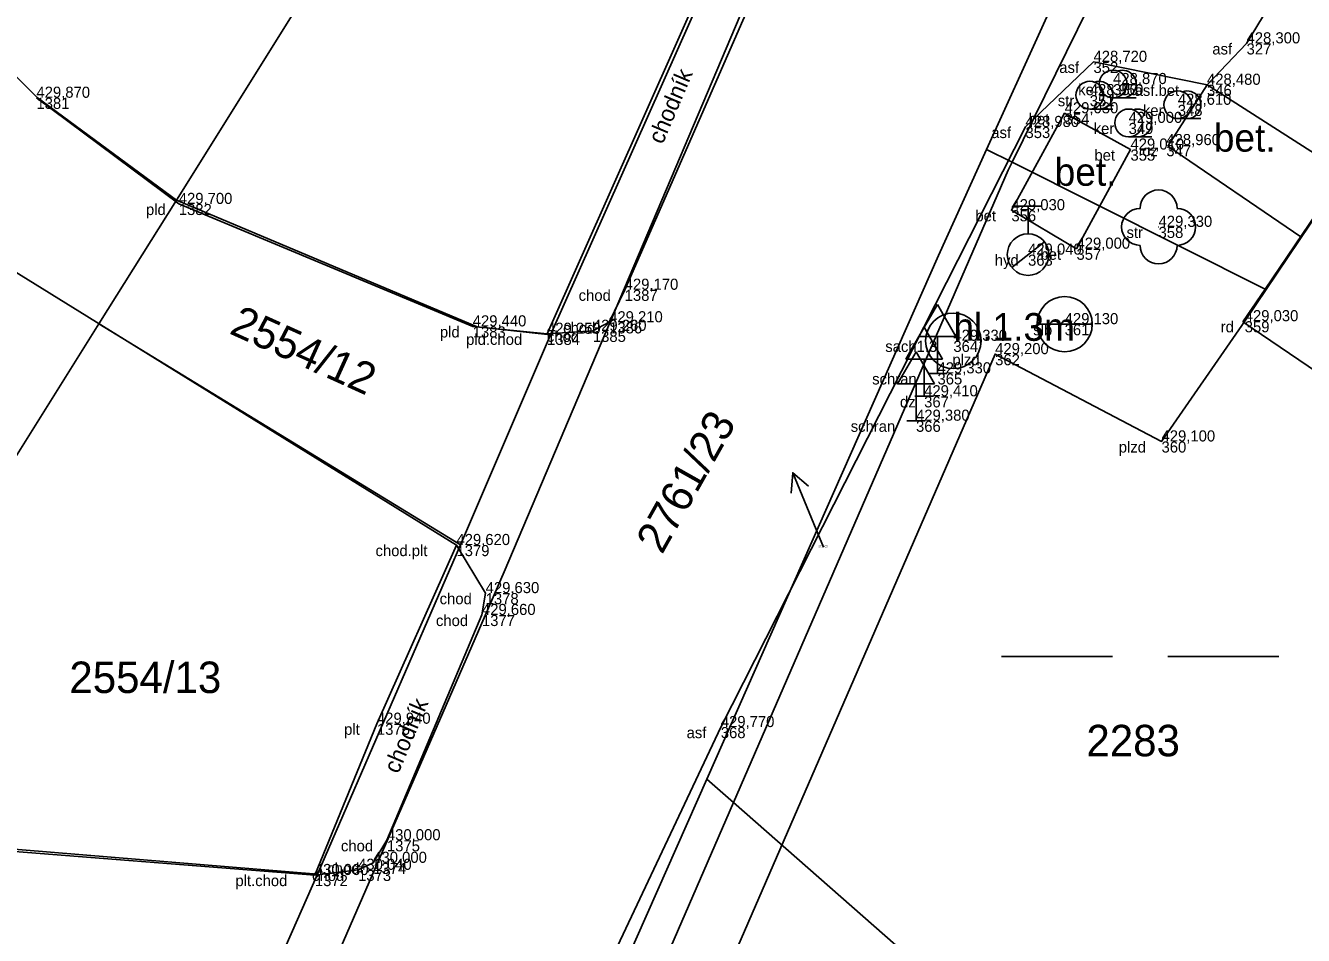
# Model space of a CAD drawing. Extents: x -747792 to -745414, y -1093712 to -1091463.
# Drawn here: x -746629.9 to -746595.34, y -1092966.57 to -1092941.98 of the extents above; entities that cross this region are included whole.
import ezdxf

# ---------------------------------------------------------------- set-up
doc = ezdxf.new("R2010")
doc.units = 0
for name, color, linetype in [('Budovy', 7, 'Continuous'), ('Doplňkové značky', 7, 'Continuous'), ('Hladina', 7, 'Continuous'), ('Koleje_dopravní prvky', 7, 'Continuous'), ('Nezařazené objekty', 7, 'Continuous'), ('Nivelační značky_hrany', 7, 'Continuous'), ('Názvy obcí_ulic', 7, 'Continuous'), ('Popisy objektů_povrchů', 7, 'Continuous'), ('Pracovní_bod JDTM STC_VC - výška', 7, 'Continuous'), ('Pracovní_bod PPBP - číslo', 7, 'Continuous'), ('Pracovní_bod ZPBP - číslo', 7, 'Continuous'), ('Rozhraní ploch', 7, 'Continuous'), ('Stromy_porost', 7, 'Continuous'), ('Výškopis', 7, 'Continuous'), ('Čísla popisná_parcelní', 7, 'Continuous')]:
    doc.layers.add(name, color=color, linetype=linetype)

msp = doc.modelspace()

# ---------------------------------------------------------------- linework, layer by layer
at = {"layer": 'Budovy'}
for points in [[(-746603.51, -1092959.03), (-746600.51, -1092959.03)], [(-746599.01, -1092959.03), (-746596.01, -1092959.03)]]:
    msp.add_lwpolyline(points, dxfattribs=at)
at = {"layer": 'Doplňkové značky'}
for points in [[(-746609.194, -1092954.622), (-746609.155, -1092954.064), (-746608.732, -1092954.431)], [(-746609.155, -1092954.064), (-746608.58, -1092955.45)], [(-746608.32, -1092956.08), (-746608.58, -1092955.45)]]:
    msp.add_lwpolyline(points, dxfattribs=at)
at = {"layer": 'Hladina'}
for p, q in [((-746596.88, -1092942.46), (-746596.88, -1092942.46)), ((-746601.02, -1092942.96), (-746601.02, -1092942.96)), ((-746600.49, -1092943.56), (-746600.49, -1092943.56)), ((-746597.95, -1092943.58), (-746597.95, -1092943.58)), ((-746629.61, -1092943.93), (-746629.61, -1092943.93)), ((-746601.12, -1092943.86), (-746601.12, -1092943.86)), ((-746598.74, -1092944.12), (-746598.74, -1092944.12)), ((-746601.8, -1092944.35), (-746601.8, -1092944.35)), ((-746600.07, -1092944.61), (-746600.07, -1092944.61)), ((-746602.86, -1092944.72), (-746602.86, -1092944.72)), ((-746600.02, -1092945.33), (-746600.02, -1092945.33)), ((-746599.05, -1092945.21), (-746599.05, -1092945.21)), ((-746625.76, -1092946.8), (-746625.76, -1092946.8)), ((-746603.24, -1092946.97), (-746603.24, -1092946.97)), ((-746599.26, -1092947.42), (-746599.26, -1092947.42)), ((-746601.48, -1092948.01), (-746601.48, -1092948.01)), ((-746602.79, -1092948.17), (-746602.79, -1092948.17)), ((-746613.7, -1092949.12), (-746613.7, -1092949.12)), ((-746617.81, -1092950.11), (-746617.81, -1092950.11)), ((-746614.12, -1092950), (-746614.12, -1092950)), ((-746601.8, -1092950.05), (-746601.8, -1092950.05)), ((-746596.93, -1092949.97), (-746596.93, -1092949.97)), ((-746615.8, -1092950.31), (-746615.8, -1092950.31)), ((-746614.56, -1092950.23), (-746614.56, -1092950.23)), ((-746604.81, -1092950.5), (-746604.81, -1092950.5)), ((-746603.68, -1092950.86), (-746603.68, -1092950.86)), ((-746605.24, -1092951.38), (-746605.24, -1092951.38)), ((-746605.6, -1092952), (-746605.6, -1092952)), ((-746605.82, -1092952.66), (-746605.82, -1092952.66)), ((-746599.18, -1092953.22), (-746599.18, -1092953.22)), ((-746618.25, -1092956.02), (-746618.25, -1092956.02)), ((-746617.46, -1092957.32), (-746617.46, -1092957.32)), ((-746617.56, -1092957.91), (-746617.56, -1092957.91)), ((-746620.4, -1092960.85), (-746620.4, -1092960.85)), ((-746611.1, -1092960.94), (-746611.1, -1092960.94)), ((-746620.13, -1092964), (-746620.13, -1092964)), ((-746620.5, -1092964.61), (-746620.5, -1092964.61)), ((-746622.08, -1092964.94), (-746622.08, -1092964.94)), ((-746620.91, -1092964.8), (-746620.91, -1092964.8))]:
    msp.add_line(p, q, dxfattribs=at)
at = {"layer": 'Nezařazené objekty'}
for points in [[(-746629.61, -1092943.93), (-746625.76, -1092946.8), (-746617.81, -1092950.11), (-746615.8, -1092950.31), (-746607.89, -1092932.54), (-746608.65, -1092931.35)], [(-746599.01, -1092945.24), (-746595.41, -1092947.69)], [(-746639.49, -1092962.88), (-746634.89, -1092963.93), (-746622.08, -1092964.94), (-746620.4, -1092960.85), (-746618.25, -1092956.02), (-746632.9, -1092946.96)], [(-746596.93, -1092949.97), (-746599.18, -1092953.22), (-746603.68, -1092950.86), (-746611.12, -1092967.97), (-746609.88, -1092968.61)]]:
    msp.add_lwpolyline(points, dxfattribs=at)
at = {"layer": 'Nivelační značky_hrany'}
for points in [[(-746567.47, -1092928.76), (-746566.95, -1092927.82), (-746569.47, -1092926.26), (-746577.49, -1092922.09), (-746580.71, -1092921), (-746582.05, -1092920.75), (-746583.67, -1092921.02), (-746585.64, -1092922.33), (-746587.16, -1092923.77), (-746589.64, -1092927.2), (-746592.28, -1092931.27), (-746593.72, -1092934.95), (-746594.32, -1092936.39), (-746593.98, -1092937.68), (-746596.88, -1092942.46), (-746597.95, -1092943.58)], [(-746615.8, -1092950.31), (-746614.56, -1092950.23), (-746614.12, -1092950), (-746613.7, -1092949.12), (-746606.9, -1092933.61), (-746606.5, -1092932.47), (-746606.65, -1092931.53), (-746607.26, -1092930.61), (-746608.07, -1092930.18)], [(-746613, -1092975.05), (-746615.68, -1092973.55), (-746616.37, -1092972.41), (-746614.88, -1092968.94), (-746611.1, -1092960.94), (-746602.86, -1092944.72), (-746601.02, -1092942.96), (-746597.95, -1092943.58)], [(-746599.01, -1092945.24), (-746597.95, -1092943.58), (-746594.24, -1092945.95)], [(-746601.48, -1092948.01), (-746603.24, -1092946.97), (-746601.8, -1092944.35), (-746600.02, -1092945.33), (-746601.48, -1092948.01)], [(-746622.08, -1092964.94), (-746620.91, -1092964.8), (-746620.5, -1092964.61), (-746620.13, -1092964), (-746617.56, -1092957.91), (-746617.46, -1092957.32), (-746618.25, -1092956.02)]]:
    msp.add_lwpolyline(points, dxfattribs=at)
at = {"layer": 'Názvy obcí_ulic'}
for p, q in [((-746605.24, -1092949.514), (-746605.74, -1092950.38)), ((-746605.24, -1092949.514), (-746604.74, -1092950.38)), ((-746605.6, -1092950.134), (-746606.1, -1092951)), ((-746605.6, -1092950.134), (-746605.1, -1092951)), ((-746605.74, -1092950.38), (-746604.74, -1092950.38)), ((-746605.24, -1092951.38), (-746605.24, -1092950.38)), ((-746605.82, -1092950.794), (-746606.32, -1092951.66)), ((-746605.82, -1092950.794), (-746605.32, -1092951.66)), ((-746606.1, -1092951), (-746605.1, -1092951)), ((-746605.6, -1092952), (-746605.6, -1092951)), ((-746605.49, -1092951.38), (-746604.99, -1092951.38)), ((-746606.32, -1092951.66), (-746605.32, -1092951.66)), ((-746605.82, -1092952.66), (-746605.82, -1092951.66)), ((-746605.85, -1092952), (-746605.35, -1092952)), ((-746606.07, -1092952.66), (-746605.57, -1092952.66))]:
    msp.add_line(p, q, dxfattribs=at)
at = {"layer": 'Popisy objektů_povrchů'}
msp.add_lwpolyline([(-746596.93, -1092949.97), (-746593.705, -1092945.189)], dxfattribs=at)
at = {"layer": 'Pracovní_bod JDTM STC_VC - výška'}
msp.add_circle((-746599.26, -1092947.42), 0.0005, dxfattribs=at)
for centre, start, end in [((-746599.26, -1092946.92), 0, 180), ((-746599.76, -1092947.42), 90, 270), ((-746598.76, -1092947.42), 270, 90), ((-746599.26, -1092947.92), 180, 360)]:
    msp.add_arc(centre, 0.5, start, end, dxfattribs=at)
at = {"layer": 'Pracovní_bod PPBP - číslo'}
for p, q in [((-746600.49, -1092943.935), (-746599.865, -1092943.935)), ((-746601.12, -1092944.235), (-746600.495, -1092944.235)), ((-746598.74, -1092944.495), (-746598.115, -1092944.495)), ((-746600.07, -1092944.985), (-746599.445, -1092944.985))]:
    msp.add_line(p, q, dxfattribs=at)
for centre in [(-746600.49, -1092943.56), (-746601.12, -1092943.86), (-746598.74, -1092944.12), (-746600.07, -1092944.61)]:
    msp.add_circle(centre, 0.375, dxfattribs=at)
for centre in [(-746600.24, -1092943.56), (-746600.87, -1092943.86), (-746598.49, -1092944.12), (-746599.82, -1092944.61)]:
    msp.add_arc(centre, 0.375, 249.4944, 109.0474, dxfattribs=at)
at = {"layer": 'Stromy_porost'}
for points in [[(-746604.07, -1092926.36), (-746616.96, -1092956.74)], [(-746595.86, -1092930.73), (-746603.22, -1092945.67)], [(-746607.76, -1092932.52), (-746615.71, -1092950.34)], [(-746603.91, -1092945.33), (-746600.83, -1092938.54)], [(-746596.38, -1092949.1), (-746589.37, -1092938.75)], [(-746634.6, -1092938.92), (-746629.59, -1092943.92)], [(-746625.82, -1092946.7), (-746622.69, -1092941.7)], [(-746629.59, -1092943.92), (-746625.82, -1092946.7)], [(-746603.91, -1092945.33), (-746605.21, -1092948.19)], [(-746603.91, -1092945.33), (-746603.22, -1092945.67)], [(-746603.22, -1092945.67), (-746603.33, -1092945.89)], [(-746603.22, -1092945.67), (-746596.38, -1092949.1)], [(-746603.33, -1092945.89), (-746610.76, -1092962.98)], [(-746627.92, -1092950.04), (-746625.82, -1092946.7)], [(-746625.82, -1092946.7), (-746617.69, -1092950.12)], [(-746605.21, -1092948.19), (-746611.48, -1092962.35)], [(-746596.98, -1092949.99), (-746596.38, -1092949.1)], [(-746632.12, -1092956.74), (-746627.92, -1092950.04)], [(-746627.92, -1092950.04), (-746618.14, -1092956.01)], [(-746617.69, -1092950.12), (-746615.71, -1092950.34)], [(-746596.98, -1092949.99), (-746588.62, -1092955.65)], [(-746615.71, -1092950.34), (-746618.14, -1092956.01)], [(-746618.14, -1092956.01), (-746622.01, -1092964.92)], [(-746616.96, -1092956.74), (-746628.34, -1092982.88)], [(-746611.48, -1092962.35), (-746618.21, -1092977.55)], [(-746610.76, -1092962.98), (-746611.48, -1092962.35)], [(-746610.76, -1092962.98), (-746619.05, -1092982.07)], [(-746598.85, -1092973.44), (-746610.76, -1092962.98)], [(-746622.01, -1092964.92), (-746634.82, -1092963.86)], [(-746622.01, -1092964.92), (-746629.27, -1092981.35)]]:
    msp.add_lwpolyline(points, dxfattribs=at)
at = {"layer": 'Čísla popisná_parcelní'}
for p, q in [((-746603.165, -1092946.857), (-746602.415, -1092946.857)), ((-746602.79, -1092947.607), (-746602.79, -1092946.857)), ((-746603.231, -1092948.516), (-746602.346, -1092947.822)), ((-746601.052, -1092950.05), (-746602.547, -1092950.05))]:
    msp.add_line(p, q, dxfattribs=at)
for centre, radius in [((-746602.79, -1092948.17), 0.562), ((-746604.81, -1092950.5), 0.75)]:
    msp.add_circle(centre, radius, dxfattribs=at)
for start, end in [(0, 180), (180, 0)]:
    msp.add_arc((-746601.8, -1092950.05), 0.747, start, end, dxfattribs=at)

# ---------------------------------------------------------------- texts
at = {"layer": 'Doplňkové značky'}
msp.add_text('2761/23', height=0.85, rotation=60.5616, dxfattribs=at).set_placement((-746612.689, -1092956.296))
at = {"layer": 'Koleje_dopravní prvky'}
msp.add_text('2554/12', height=0.85, rotation=335.6387, dxfattribs=at).set_placement((-746624.423, -1092950.29))
for s, height, p in [('2761/23', 0.05, (-746608.457, -1092956.08)), ('2554/13', 0.85, (-746628.719, -1092960.02)), ('2283', 0.85, (-746601.212, -1092961.73))]:
    msp.add_text(s, height=height, dxfattribs=at).set_placement(p)
at = {"layer": 'Pracovní_bod ZPBP - číslo'}
for s, height, rotation, p in [('chodník', 0.45, 67.0213, (-746612.674, -1092945.209)), ('bet.', 0.75, 0.0578, (-746597.766, -1092945.387)), ('bet.', 0.75, 0.0578, (-746602.071, -1092946.31)), ('chodník', 0.45, 67.0213, (-746619.824, -1092962.224))]:
    msp.add_text(s, height=height, rotation=rotation, dxfattribs=at).set_placement(p)
msp.add_text('hl.1.3m', height=0.75, dxfattribs=at).set_placement((-746604.81, -1092950.5))
at = {"layer": 'Rozhraní ploch'}
for s, p in [(' asf', (-746597.917, -1092942.76)), ('327', (-746596.88, -1092942.76)), (' asf', (-746602.057, -1092943.26)), ('352', (-746601.02, -1092943.26)), (' ker', (-746601.546, -1092943.86)), ('350', (-746600.49, -1092943.86)), (' asf.bet', (-746600.019, -1092943.88)), ('346', (-746597.95, -1092943.88)), ('1381', (-746629.61, -1092944.23)), (' str', (-746602.098, -1092944.16)), ('351', (-746601.12, -1092944.16)), (' ker', (-746599.796, -1092944.42)), ('348', (-746598.74, -1092944.42)), (' bet', (-746602.886, -1092944.65)), ('354', (-746601.8, -1092944.65)), (' ker', (-746601.126, -1092944.91)), ('349', (-746600.07, -1092944.91)), (' asf', (-746603.897, -1092945.02)), ('353', (-746602.86, -1092945.02)), (' bet', (-746601.106, -1092945.63)), ('355', (-746600.02, -1092945.63)), (' oz', (-746599.815, -1092945.51)), ('347', (-746599.05, -1092945.51)), (' pld', (-746626.759, -1092947.1)), ('1382', (-746625.76, -1092947.1)), (' bet', (-746604.326, -1092947.27)), ('356', (-746603.24, -1092947.27)), ('358', (-746599.26, -1092947.72)), (' str', (-746600.238, -1092947.72)), (' bet', (-746602.566, -1092948.31)), ('357', (-746601.48, -1092948.31)), (' hyd', (-746603.801, -1092948.47)), ('363', (-746602.79, -1092948.47)), (' chod', (-746615.056, -1092949.42)), ('1387', (-746613.7, -1092949.42)), (' pld', (-746618.809, -1092950.41)), ('1383', (-746617.81, -1092950.41)), (' chod', (-746615.476, -1092950.3)), ('1386', (-746614.12, -1092950.3)), (' slb', (-746602.761, -1092950.35)), ('361', (-746601.8, -1092950.35)), (' rd', (-746597.691, -1092950.27)), ('359', (-746596.93, -1092950.27)), (' pld.chod', (-746618.1, -1092950.61)), (' chod', (-746615.916, -1092950.53)), ('1384', (-746615.8, -1092950.61)), ('1385', (-746614.56, -1092950.53)), (' sach1.3', (-746606.763, -1092950.8)), ('364', (-746604.81, -1092950.8)), (' plzd', (-746604.948, -1092951.16)), ('362', (-746603.68, -1092951.16)), (' schran', (-746607.118, -1092951.68)), ('365', (-746605.24, -1092951.68)), (' dz', (-746606.365, -1092952.3)), ('367', (-746605.6, -1092952.3)), (' schran', (-746607.698, -1092952.96)), ('366', (-746605.82, -1092952.96)), (' plzd', (-746600.448, -1092953.52)), ('360', (-746599.18, -1092953.52)), (' chod.plt', (-746620.55, -1092956.32)), ('1379', (-746618.25, -1092956.32)), (' chod', (-746618.816, -1092957.62)), ('1378', (-746617.46, -1092957.62)), (' chod', (-746618.916, -1092958.21)), ('1377', (-746617.56, -1092958.21)), (' plt', (-746621.399, -1092961.15)), ('1376', (-746620.4, -1092961.15)), (' asf', (-746612.137, -1092961.24)), ('368', (-746611.1, -1092961.24)), (' chod', (-746621.486, -1092964.3)), ('1375', (-746620.13, -1092964.3)), (' chod', (-746621.856, -1092964.91)), ('1374', (-746620.5, -1092964.91)), (' plt.chod', (-746624.34, -1092965.24)), (' chod', (-746622.266, -1092965.1)), ('1372', (-746622.08, -1092965.24)), ('1373', (-746620.91, -1092965.1))]:
    msp.add_text(s, height=0.3, dxfattribs=at).set_placement(p)
at = {"layer": 'Výškopis'}
for s, p in [('428,300', (-746596.88, -1092942.46)), ('428,720', (-746601.02, -1092942.96)), ('428,870', (-746600.49, -1092943.56)), ('428,950', (-746601.12, -1092943.86)), ('428,480', (-746597.95, -1092943.58)), ('429,870', (-746629.61, -1092943.93)), ('428,610', (-746598.74, -1092944.12)), ('429,030', (-746601.8, -1092944.35)), ('429,000', (-746600.07, -1092944.61)), ('428,980', (-746602.86, -1092944.72)), ('428,960', (-746599.05, -1092945.21)), ('429,010', (-746600.02, -1092945.33)), ('429,700', (-746625.76, -1092946.8)), ('429,030', (-746603.24, -1092946.97)), ('429,330', (-746599.26, -1092947.42)), ('429,000', (-746601.48, -1092948.01)), ('429,040', (-746602.79, -1092948.17)), ('429,170', (-746613.7, -1092949.12)), ('429,440', (-746617.81, -1092950.11)), ('429,210', (-746614.12, -1092950)), ('429,130', (-746601.8, -1092950.05)), ('429,030', (-746596.93, -1092949.97)), ('429,250', (-746615.8, -1092950.31)), ('429,260', (-746614.56, -1092950.23)), ('429,330', (-746604.81, -1092950.5)), ('429,200', (-746603.68, -1092950.86)), ('429,330', (-746605.24, -1092951.38)), ('429,410', (-746605.6, -1092952)), ('429,380', (-746605.82, -1092952.66)), ('429,100', (-746599.18, -1092953.22)), ('429,620', (-746618.25, -1092956.02)), ('429,630', (-746617.46, -1092957.32)), ('429,660', (-746617.56, -1092957.91)), ('429,940', (-746620.4, -1092960.85)), ('429,770', (-746611.1, -1092960.94)), ('430,000', (-746620.13, -1092964)), ('430,000', (-746620.5, -1092964.61)), ('430,060', (-746622.08, -1092964.94)), ('430,040', (-746620.91, -1092964.8))]:
    msp.add_text(s, height=0.3, dxfattribs=at).set_placement(p)

doc.saveas('drawing.dxf')
